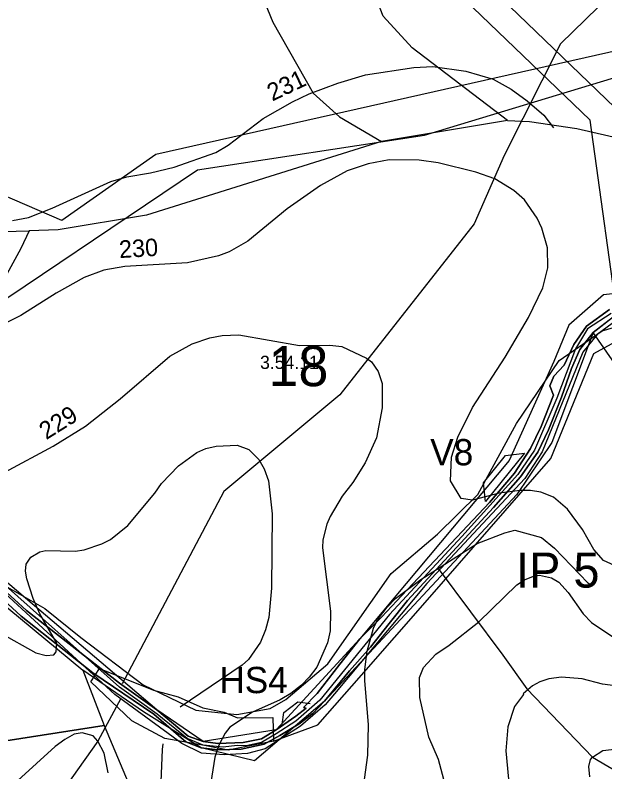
# Model space of a CAD drawing. Extents: x -662500 to -655523, y -1056000 to -1049993.
# Drawn here: x -661062 to -660725.5, y -1053298.7 to -1052866.9 of the extents above; entities that cross this region are included whole.
import ezdxf

# ---------------------------------------------------------------- set-up
doc = ezdxf.new("R2010")
doc.units = 0
for name, color, linetype in [('Vrstva 12', 7, 'Continuous'), ('Vrstva 17', 7, 'Continuous'), ('Vrstva 24', 7, 'Continuous'), ('Vrstva 37', 7, 'Continuous'), ('Vrstva 5', 7, 'Continuous'), ('Vrstva 51', 7, 'Continuous'), ('Vrstva 52', 7, 'Continuous'), ('Vrstva 57', 7, 'Continuous'), ('Vrstva 61', 7, 'Continuous'), ('Vrstva 7', 7, 'Continuous')]:
    doc.layers.add(name, color=color, linetype=linetype)

# ---------------------------------------------------------------- blocks, each defined once
blk = doc.blocks.new('PSZ019')
at = {"layer": 'Vrstva 17'}
blk.add_lwpolyline([(-10, -5), (-5, 0), (5, 0), (10, -5)], dxfattribs=at)

msp = doc.modelspace()

# ---------------------------------------------------------------- linework, layer by layer
at = {"layer": 'Vrstva 12'}
msp.add_lwpolyline([(-660721.83, -1053037.12), (-660735.32, -1053045.86), (-660742.25, -1053057.37), (-660752.91, -1053085.48), (-660765.65, -1053115.09), (-660775.15, -1053129.03), (-660807.08, -1053164.33), (-660848.44, -1053208.87), (-660888.22, -1053257.8), (-660901.81, -1053269.79), (-660913.13, -1053277.07), (-660921.52, -1053281.95), (-660930.22, -1053283.86), (-660935.33, -1053283.77), (-660943.41, -1053284.62), (-660954.65, -1053283.42), (-660963.95, -1053279.66), (-660981, -1053265.88), (-661002.51, -1053250.47), (-661074.82, -1053186.07), (-661095.06, -1053170.24), (-661358.37, -1053118.85)], dxfattribs=at)
at = {"layer": 'Vrstva 24'}
for points in [[(-660781, -1052927), (-660835.5, -1052885.5), (-660852, -1052867.5), (-660862.5, -1052840.5), (-660865.5, -1052804.5), (-660857.5, -1052768.5), (-660841.5, -1052741.5), (-660820.5, -1052719), (-660772, -1052687), (-660756.5, -1052680), (-660742.5, -1052678), (-660707.5, -1052679.5), (-660683, -1052682)], [(-660937.5, -1052816), (-660915, -1052871), (-660892, -1052911.5), (-660877, -1052925), (-660853, -1052939)], [(-660781, -1052927), (-660853, -1052939)], [(-660781, -1052927), (-660768.5, -1052927.5), (-660741.5, -1052931.5), (-660705, -1052940), (-660651.5, -1052959), (-660597, -1052987.5), (-660574.5, -1052991.5), (-660541.5, -1052988.5), (-660487, -1052969), (-660438.5, -1052947.5), (-660420, -1052937)], [(-660853, -1052939), (-660987, -1052981), (-661037.5, -1052989.5), (-661054, -1052990)], [(-661283, -1052945), (-661192.5, -1052974.5), (-661142.5, -1052986), (-661091, -1052991), (-661054, -1052990)], [(-661054, -1052990), (-661058.86, -1053000), (-661076, -1053031), (-661094, -1053081.5), (-661099.5, -1053135.5), (-661091.5, -1053170.5), (-661086.5, -1053182), (-661045, -1053205.5), (-661024.5, -1053222), (-660989, -1053249), (-660959, -1053263.5), (-660935.5, -1053266), (-660916.5, -1053262.5), (-660907.5, -1053257.5), (-660883.5, -1053237), (-660847.5, -1053185.5), (-660821, -1053163), (-660798, -1053140.5), (-660776, -1053100), (-660751.5, -1053064), (-660727, -1053047), (-660682.5, -1053034), (-660647, -1053031.5)]]:
    msp.add_lwpolyline(points, dxfattribs=at)
at = {"layer": 'Vrstva 37'}
msp.add_lwpolyline([(-661300.67, -1052546.9), (-661245.57, -1052460.16), (-661215.38, -1052383.27), (-661093.2, -1052036.62), (-661059.91, -1052039.12), (-661052.32, -1052039.28), (-660977.8, -1052048.89), (-660913.91, -1052057.78), (-660920.61, -1052206.16), (-660810.17, -1052287.05), (-660506.62, -1052383.42), (-660536.22, -1052464.9), (-660540.27, -1052493.39), (-660540.27, -1052503.48), (-660534.66, -1052516.97), (-660434.32, -1052493.61), (-660230.57, -1052568.54), (-660284.32, -1052681.97), (-660363.46, -1052667.73), (-660573.1, -1052736.64), (-660686.93, -1052879.97), (-660981.83, -1052946.49), (-661035.35, -1052984.09), (-661278.3, -1052879.13)], dxfattribs=at)
for points in [[(-661234.06, -1053140.82), (-660958.01, -1052955.16), (-660828.41, -1052935.32), (-660688.36, -1052892.92), (-660553.31, -1052789.11), (-660369.71, -1052706.96), (-660290.66, -1052724.21), (-660337.18, -1052820.64), (-660356.48, -1052923.15), (-660446.27, -1052991.51), (-660506.13, -1053013.32), (-660608.87, -1053013.32), (-660726.31, -1053026.56), (-660746.15, -1053043.81), (-660754.61, -1053064.64), (-660780.18, -1053120.96), (-660865.36, -1053222.79), (-660913.12, -1053274.78), (-660954.8, -1053281.43), (-660981.14, -1053263.41), (-661072.84, -1053185.46), (-661116.02, -1053160.8)], [(-661023.41, -1053240.67), (-661011.27, -1053272.33), (-660950.35, -1053416.85), (-660839.76, -1053380.96), (-660793.93, -1053380.96), (-660681.35, -1053517.53), (-660634.53, -1053539.46), (-660568.77, -1053550.42), (-660547.85, -1053511.55), (-660560.8, -1053426.81), (-660514.36, -1053361.25), (-660732.12, -1053048.02), (-660755.79, -1053110.82), (-660775.71, -1053140.44), (-660885.47, -1053258.33), (-660925.44, -1053292.53), (-660955.96, -1053285.06), (-660988.72, -1053264.41)], [(-661148.54, -1053166.72), (-661115.03, -1053173.55), (-661080.22, -1053193.73), (-661023.41, -1053240.67), (-661011.27, -1053272.33), (-661177.27, -1053298.13), (-661177.27, -1053193.32)], [(-661177.27, -1053298.13), (-661011.27, -1053272.33), (-660950.35, -1053416.85), (-660917.78, -1053483.08), (-660790.25, -1053532.64), (-660747.55, -1053569.67), (-660738.48, -1053593.77), (-660814.61, -1053668.4), (-661026.54, -1053571.34), (-661076.33, -1053536.24), (-661164.49, -1053527.45), (-661164.49, -1053425.3)]]:
    msp.add_lwpolyline(points, close=True, dxfattribs=at)
at = {"layer": 'Vrstva 5'}
for points in [[(-660722.76, -1053034.93), (-660735.98, -1053044.48), (-660743.18, -1053054.83), (-660748.68, -1053066.7), (-660754.58, -1053072.87), (-660756.89, -1053078.44), (-660754.9, -1053083.79), (-660761.93, -1053101.63), (-660767.89, -1053114.23), (-660777.07, -1053128.26), (-660791.34, -1053144.98), (-660841.41, -1053198.13), (-660852.69, -1053210.31), (-660865.36, -1053222.79), (-660876.66, -1053237.26), (-660889.7, -1053254.02), (-660897.41, -1053262.02), (-660895.91, -1053262.43), (-660901.79, -1053267.02), (-660913.12, -1053274.78), (-660921.53, -1053279.8), (-660931.83, -1053281.97), (-660946.36, -1053282.49), (-660954.8, -1053281.43), (-660963.29, -1053278.32), (-660981.14, -1053263.41), (-661002.45, -1053248.05), (-661055.62, -1053206.74), (-661080.49, -1053183.96)], [(-661080.49, -1053183.96), (-661055.62, -1053206.74), (-661002.45, -1053248.05), (-660981.14, -1053263.41), (-660963.29, -1053278.32), (-660954.8, -1053281.43), (-660946.36, -1053282.49), (-660931.83, -1053281.97), (-660921.53, -1053279.8), (-660913.12, -1053274.78), (-660901.79, -1053267.02), (-660895.91, -1053262.43), (-660897.41, -1053262.02), (-660889.7, -1053254.02), (-660876.66, -1053237.26), (-660865.36, -1053222.79), (-660852.69, -1053210.31), (-660841.41, -1053198.13), (-660791.34, -1053144.98), (-660777.07, -1053128.26), (-660767.89, -1053114.23), (-660761.93, -1053101.63), (-660754.9, -1053083.79), (-660756.89, -1053078.44), (-660754.58, -1053072.87), (-660748.68, -1053066.7), (-660743.18, -1053054.83), (-660735.98, -1053044.48), (-660722.76, -1053034.93)], [(-660720.59, -1053039.07), (-660732.12, -1053048.02), (-660739.81, -1053057.74), (-660744.56, -1053068.49), (-660750.25, -1053084.96), (-660757.59, -1053103.56), (-660763.8, -1053116.25), (-660773.68, -1053130.3), (-660789.03, -1053147.8), (-660838.07, -1053200.94), (-660848.58, -1053214.08), (-660859.32, -1053227.61), (-660871.21, -1053241.16), (-660885.47, -1053258.33), (-660892.03, -1053265.26), (-660899.88, -1053271.38), (-660910.94, -1053278.04), (-660919.86, -1053282.88), (-660933.05, -1053285.84), (-660946.32, -1053286.21), (-660955.96, -1053285.06), (-660964.6, -1053281.56), (-660982.89, -1053265.85), (-661017.69, -1053242.2), (-661058.53, -1053209.95), (-661076.54, -1053193.52)], [(-661076.54, -1053193.52), (-661058.53, -1053209.95), (-661017.69, -1053242.2), (-660982.89, -1053265.85), (-660964.6, -1053281.56), (-660955.96, -1053285.06), (-660946.32, -1053286.21), (-660933.05, -1053285.84), (-660919.86, -1053282.88), (-660910.94, -1053278.04), (-660899.88, -1053271.38), (-660892.03, -1053265.26), (-660885.47, -1053258.33), (-660871.21, -1053241.16), (-660859.32, -1053227.61), (-660848.58, -1053214.08), (-660838.07, -1053200.94), (-660789.03, -1053147.8), (-660773.68, -1053130.3), (-660763.8, -1053116.25), (-660757.59, -1053103.56), (-660750.25, -1053084.96), (-660744.56, -1053068.49), (-660739.81, -1053057.74), (-660732.12, -1053048.02), (-660721.62, -1053039.87)]]:
    msp.add_lwpolyline(points, dxfattribs=at)
at = {"layer": 'Vrstva 51'}
for points in [[(-661333.87, -1052639.96), (-661030.97, -1052722.69), (-660970.26, -1052748.97), (-660859.83, -1052784.77), (-660719.81, -1052919.67), (-660703.56, -1053036.33), (-660627.44, -1053034.97), (-660487.78, -1053023.58), (-660465.78, -1053017.23), (-660435.07, -1052998.4)], [(-660435.71, -1053016.39), (-660459.67, -1053031.08), (-660485.06, -1053038.41), (-660626.7, -1053049.96), (-660716.58, -1053051.57), (-660733.95, -1052926.87), (-660867.75, -1052797.97), (-660975.56, -1052763.02), (-661035.95, -1052736.88), (-661337.82, -1052654.43)]]:
    msp.add_lwpolyline(points, dxfattribs=at)
at = {"layer": 'Vrstva 52'}
msp.add_lwpolyline([(-660914.58, -1053281.25), (-660889.24, -1053271.93), (-660864.44, -1053243.57), (-660826.77, -1053200.49), (-660756.29, -1053119.89), (-660731.82, -1053060.03), (-660717.44, -1053052.21)], dxfattribs=at)
msp.add_lwpolyline([(-661018.88, -1053247.39), (-661013.86, -1053239.75), (-660983.14, -1053252.18), (-660969.07, -1053255.98), (-660954.84, -1053262.25), (-660942.72, -1053264.73), (-660935.12, -1053267.87), (-660915.07, -1053267.7), (-660914.58, -1053281.25), (-660940.45, -1053286.36), (-660954.04, -1053283.72), (-660976.67, -1053279.76), (-660995.43, -1053269.69)], close=True, dxfattribs=at)
at = {"layer": 'Vrstva 57'}
for points in [[(-660686.61, -1052820.49), (-660750.76, -1052883.23), (-660782.95, -1052946.91), (-660800.11, -1052985.92), (-660876.71, -1053083.67), (-660942.98, -1053138.66), (-661001.03, -1053248.46)], [(-660820.67, -1053182.66), (-660783.66, -1053232.18), (-660770.03, -1053251.45), (-660732.62, -1053290.28), (-660657.94, -1053334.16), (-660629.74, -1053356.96), (-660614.23, -1053378.11), (-660607.65, -1053423.22), (-660606.24, -1053447.66)], [(-661001.72, -1053256.85), (-661014.78, -1053281.21), (-661058.43, -1053342.72), (-661096.89, -1053410.3), (-661108.64, -1053470.92)]]:
    msp.add_lwpolyline(points, dxfattribs=at)
at = {"layer": 'Vrstva 61'}
msp.add_lwpolyline([(-660718.55, -1053040.85), (-660729.86, -1053049.1), (-660738.1, -1053059.21), (-660761.33, -1053116.11), (-660771.24, -1053131.38), (-660827.02, -1053191.27), (-660879.82, -1053254.25), (-660885.04, -1053260.47), (-660899.16, -1053272.63), (-660919.42, -1053285.57), (-660929.53, -1053288.23), (-660942.75, -1053288.99), (-660955.65, -1053288.03), (-660966.97, -1053282.64), (-661005.21, -1053254.62), (-661075.25, -1053190.17), (-661096.03, -1053172.53), (-661234.7, -1053147.1), (-661269.14, -1053141.65)], dxfattribs=at)
msp.add_lwpolyline([(-660793.53, -1053144.41), (-660794.68, -1053133.86), (-660782.14, -1053118.28), (-660771.43, -1053116.93)], close=True, dxfattribs=at)
at = {"layer": 'Vrstva 7'}
for p, q in [((-660862.01, -1052900.99), (-660834.51, -1052896.74)), ((-660834.51, -1052896.74), (-660823.74, -1052896.17)), ((-660823.74, -1052896.17), (-660804.89, -1052898.86)), ((-660804.89, -1052898.86), (-660789.16, -1052903.4)), ((-660877.88, -1052905.8), (-660862.01, -1052900.99)), ((-660789.16, -1052903.4), (-660778.96, -1052909.21)), ((-660894.18, -1052911.76), (-660877.88, -1052905.8)), ((-660903.75, -1052916.29), (-660894.18, -1052911.76)), ((-660778.96, -1052909.21), (-660769.89, -1052915.73)), ((-660920.53, -1052925.93), (-660903.75, -1052916.29)), ((-660769.89, -1052915.73), (-660760.4, -1052923.94)), ((-660940.52, -1052941.09), (-660920.53, -1052925.93)), ((-660760.4, -1052923.94), (-660754.73, -1052931.17)), ((-660947.6, -1052945.34), (-660940.52, -1052941.09)), ((-660971.27, -1052953.56), (-660947.6, -1052945.34)), ((-660860.59, -1052951.72), (-660872.49, -1052955.69)), ((-660848.68, -1052949.45), (-660860.59, -1052951.72)), ((-660831.4, -1052949.59), (-660848.68, -1052949.45)), ((-660820.62, -1052951.15), (-660831.4, -1052949.59)), ((-660799.08, -1052956.54), (-660820.62, -1052951.15)), ((-660984.73, -1052956.96), (-660971.27, -1052953.56)), ((-660872.49, -1052955.69), (-660887.8, -1052964.05)), ((-661007.41, -1052961.92), (-660998.34, -1052959.23)), ((-660998.34, -1052959.23), (-660984.73, -1052956.96)), ((-660788.31, -1052960.37), (-660799.08, -1052956.54)), ((-660777.54, -1052967.03), (-660788.31, -1052960.37)), ((-661040.85, -1052977.09), (-661007.41, -1052961.92)), ((-660887.8, -1052964.05), (-660906.79, -1052977.37)), ((-660771.31, -1052972.27), (-660777.54, -1052967.03)), ((-660764.22, -1052982.76), (-660771.31, -1052972.27)), ((-661054.46, -1052982.47), (-661040.85, -1052977.09)), ((-660906.79, -1052977.37), (-660929.18, -1052995.79)), ((-661063.53, -1052984.17), (-661054.46, -1052982.47)), ((-660761.53, -1052988.43), (-660764.22, -1052982.76)), ((-660758.27, -1052999.76), (-660761.53, -1052988.43)), ((-660929.18, -1052995.79), (-660939.95, -1053001.89)), ((-660939.95, -1053001.89), (-660945.9, -1053004.3)), ((-660758.13, -1053011.1), (-660758.27, -1052999.76)), ((-660963.76, -1053008.27), (-660999.47, -1053010.39)), ((-660945.9, -1053004.3), (-660963.76, -1053008.27)), ((-661011.38, -1053012.38), (-661022.71, -1053016.63)), ((-660999.47, -1053010.39), (-661011.38, -1053012.38)), ((-660760.82, -1053022.44), (-660758.13, -1053011.1)), ((-661022.71, -1053016.63), (-661038.58, -1053025.55)), ((-661038.58, -1053025.55), (-661058.71, -1053038.31)), ((-660769.04, -1053039.44), (-660760.82, -1053022.44)), ((-661058.71, -1053038.31), (-661069.48, -1053043.7)), ((-660782.36, -1053062.12), (-660769.04, -1053039.44)), ((-660960.92, -1053054.47), (-660951, -1053051.06)), ((-660951, -1053051.06), (-660943.92, -1053049.65)), ((-660943.92, -1053049.65), (-660934.42, -1053049.36)), ((-660934.42, -1053049.36), (-660899.7, -1053055.46)), ((-660973.68, -1053061.55), (-660960.92, -1053054.47)), ((-660899.7, -1053055.46), (-660882.41, -1053055.31)), ((-660882.41, -1053055.31), (-660875.61, -1053056.02)), ((-660875.61, -1053056.02), (-660861.44, -1053062.68)), ((-661002.16, -1053085.78), (-660973.68, -1053061.55)), ((-660861.44, -1053062.68), (-660858.75, -1053064.81)), ((-660801.07, -1053090.75), (-660782.36, -1053062.12)), ((-660858.75, -1053064.81), (-660854.92, -1053070.34)), ((-660854.92, -1053070.34), (-660852.65, -1053077.14)), ((-660852.65, -1053077.14), (-660852.51, -1053091.03)), ((-661021.86, -1053101.37), (-661002.16, -1053085.78)), ((-660852.51, -1053091.03), (-660855.77, -1053108.18)), ((-660809.43, -1053107.75), (-660801.07, -1053090.75)), ((-661040.29, -1053112.85), (-661021.86, -1053101.37)), ((-660855.77, -1053108.18), (-660862.2, -1053122.38)), ((-660813.11, -1053119.09), (-660809.43, -1053107.75)), ((-661067.92, -1053127.73), (-661040.29, -1053112.85)), ((-660958.37, -1053116.54), (-660953.27, -1053114.27)), ((-660953.27, -1053114.27), (-660947.32, -1053112.85)), ((-660947.32, -1053112.85), (-660935.42, -1053112.28)), ((-660935.42, -1053112.28), (-660928.61, -1053114.7)), ((-660928.61, -1053114.7), (-660922.94, -1053120.51)), ((-660968.86, -1053124.19), (-660958.37, -1053116.54)), ((-660922.94, -1053120.51), (-660919.83, -1053125.89)), ((-660813.54, -1053132.69), (-660813.11, -1053119.09)), ((-660978.5, -1053134.11), (-660968.86, -1053124.19)), ((-660862.2, -1053122.38), (-660869.38, -1053133.69)), ((-660919.83, -1053125.89), (-660917.42, -1053132.69)), ((-660917.42, -1053132.69), (-660915.43, -1053151.4)), ((-660807.45, -1053142.76), (-660813.54, -1053132.69)), ((-660982.32, -1053139.78), (-660978.5, -1053134.11)), ((-660869.38, -1053133.69), (-660875.47, -1053141.48)), ((-660997.77, -1053158.2), (-660982.32, -1053139.78)), ((-660875.47, -1053141.48), (-660882.27, -1053153.1)), ((-660785.76, -1053139.78), (-660801.07, -1053143.75)), ((-660773.86, -1053138.08), (-660785.76, -1053139.78)), ((-660767.91, -1053138.08), (-660773.86, -1053138.08)), ((-660761.95, -1053139.07), (-660767.91, -1053138.08)), ((-660754.73, -1053141.9), (-660761.95, -1053139.07)), ((-660746.79, -1053148.85), (-660754.73, -1053141.9)), ((-660801.07, -1053143.75), (-660807.45, -1053142.76)), ((-660738.29, -1053160.47), (-660746.79, -1053148.85)), ((-660915.43, -1053151.4), (-660915.72, -1053193.91)), ((-660882.27, -1053153.1), (-660884.11, -1053157.35)), ((-661007.69, -1053166.14), (-660997.77, -1053158.2)), ((-660884.11, -1053157.35), (-660886.38, -1053166.28)), ((-660798.38, -1053168.41), (-660782.64, -1053162.31)), ((-660782.64, -1053162.31), (-660776.83, -1053160.75)), ((-660776.83, -1053160.75), (-660761.64, -1053165.03)), ((-660731.77, -1053171.81), (-660738.29, -1053160.47)), ((-661012.51, -1053168.69), (-661007.69, -1053166.14)), ((-660886.38, -1053166.28), (-660886.66, -1053170.81)), ((-660761.64, -1053165.03), (-660754.16, -1053171.1)), ((-661047.94, -1053173.22), (-661044.54, -1053172.37)), ((-661044.54, -1053172.37), (-661027.81, -1053172.8)), ((-661027.81, -1053172.8), (-661022.71, -1053171.95)), ((-661022.71, -1053171.95), (-661012.51, -1053168.69)), ((-660886.66, -1053170.81), (-660882.13, -1053206.95)), ((-660830.55, -1053188.95), (-660798.38, -1053168.41)), ((-660754.16, -1053171.1), (-660735.17, -1053190.8)), ((-660726.24, -1053178.18), (-660731.77, -1053171.81)), ((-661055.73, -1053180.17), (-661053.04, -1053176.2)), ((-661053.04, -1053176.2), (-661047.94, -1053173.22)), ((-661056.16, -1053184.14), (-661055.73, -1053180.17)), ((-660715.75, -1053182.86), (-660726.24, -1053178.18)), ((-661055.45, -1053188.53), (-661056.16, -1053184.14)), ((-661051.76, -1053199.87), (-661055.45, -1053188.53)), ((-660845, -1053199.73), (-660830.55, -1053188.95)), ((-660775.7, -1053191.93), (-660771.31, -1053189.1)), ((-660771.31, -1053189.1), (-660766.2, -1053187.11)), ((-660766.2, -1053187.11), (-660762.8, -1053186.54)), ((-660762.8, -1053186.54), (-660756, -1053188.1)), ((-660756, -1053188.1), (-660751.75, -1053190.51)), ((-660915.72, -1053193.91), (-660917.28, -1053210.64)), ((-660797.38, -1053213.05), (-660775.7, -1053191.93)), ((-660751.75, -1053190.51), (-660746.51, -1053196.47)), ((-660735.17, -1053190.8), (-660732.9, -1053192.21)), ((-660746.51, -1053196.47), (-660737.86, -1053208.65)), ((-661047.94, -1053208.65), (-661051.76, -1053199.87)), ((-660849.68, -1053204.69), (-660845, -1053199.73)), ((-660882.13, -1053206.95), (-660882.27, -1053218.29)), ((-660855.25, -1053212.04), (-660849.68, -1053204.69)), ((-661038.16, -1053225.23), (-661047.94, -1053208.65)), ((-660917.28, -1053210.64), (-660919.12, -1053217.72)), ((-660737.86, -1053208.65), (-660733.04, -1053213.47)), ((-660857.52, -1053216.65), (-660855.25, -1053212.04)), ((-660814.39, -1053226.37), (-660797.38, -1053213.05)), ((-660733.04, -1053213.47), (-660719.72, -1053222.4)), ((-661070.75, -1053219.42), (-661050.2, -1053230.76)), ((-660919.12, -1053217.72), (-660922.09, -1053224.81)), ((-660882.27, -1053218.29), (-660883.83, -1053225.09)), ((-660861.21, -1053229.89), (-660857.52, -1053216.65)), ((-661038.58, -1053230.19), (-661038.16, -1053225.23)), ((-660922.09, -1053224.81), (-660928.9, -1053234.59)), ((-660883.83, -1053225.09), (-660889.92, -1053238.98)), ((-660822.04, -1053231.61), (-660814.39, -1053226.37)), ((-661050.2, -1053230.76), (-661044.25, -1053232.32)), ((-661044.25, -1053232.32), (-661040, -1053231.89)), ((-661040, -1053231.89), (-661038.58, -1053230.19)), ((-660862.43, -1053240.26), (-660861.21, -1053229.89)), ((-660828.98, -1053239.12), (-660822.04, -1053231.61)), ((-660928.9, -1053234.59), (-660932.44, -1053237.85)), ((-660932.44, -1053237.85), (-660967.79, -1053261.85)), ((-660889.92, -1053238.98), (-660894.18, -1053244.65)), ((-660862.43, -1053246.63), (-660862.43, -1053240.26)), ((-660831.27, -1053244.94), (-660828.98, -1053239.12)), ((-660894.18, -1053244.65), (-660898.57, -1053249.18)), ((-660831.11, -1053256.27), (-660831.27, -1053244.94)), ((-660757.42, -1053245.73), (-660762.65, -1053247.33)), ((-660750.19, -1053244.65), (-660757.42, -1053245.73)), ((-660738.43, -1053245.64), (-660750.19, -1053244.65)), ((-660726.81, -1053248.76), (-660738.43, -1053245.64)), ((-660898.57, -1053249.18), (-660904.8, -1053254)), ((-660860.31, -1053271.86), (-660862.43, -1053246.63)), ((-660766.75, -1053249.73), (-660772.16, -1053254.14)), ((-660762.65, -1053247.33), (-660766.75, -1053249.73)), ((-660712.92, -1053250.6), (-660726.81, -1053248.76)), ((-660904.8, -1053254), (-660910.76, -1053257.54)), ((-660772.16, -1053254.14), (-660771.87, -1053254.57)), ((-660910.76, -1053257.54), (-660926.63, -1053264.63)), ((-660826.01, -1053278.94), (-660831.11, -1053256.27)), ((-660771.87, -1053254.57), (-660777.12, -1053261.51)), ((-660777.12, -1053261.51), (-660780.8, -1053272.99)), ((-660926.63, -1053264.63), (-660939.52, -1053273.28)), ((-660939.52, -1053273.28), (-660942.22, -1053276.68)), ((-660860.73, -1053289.29), (-660860.31, -1053271.86)), ((-660780.8, -1053272.99), (-660781.94, -1053286.74)), ((-661033.77, -1053280.22), (-661039.15, -1053284.33)), ((-661028.38, -1053277.24), (-661033.77, -1053280.22)), ((-661023.85, -1053276.53), (-661028.38, -1053277.24)), ((-661017.47, -1053278.09), (-661023.85, -1053276.53)), ((-661014.78, -1053281.21), (-661017.47, -1053278.09)), ((-660942.22, -1053276.68), (-660945.76, -1053283.48)), ((-660820.48, -1053291.7), (-660826.01, -1053278.94)), ((-661039.15, -1053284.33), (-661060.55, -1053303.6)), ((-661011.23, -1053288.01), (-661014.78, -1053281.21)), ((-660977.83, -1053282.67), (-660978.07, -1053286.03)), ((-660945.76, -1053283.48), (-660948.17, -1053290.28)), ((-661008.97, -1053299.35), (-661011.23, -1053288.01)), ((-660978.07, -1053286.03), (-660979.63, -1053321.74)), ((-660781.94, -1053286.74), (-660779.24, -1053315.79)), ((-660732.62, -1053290.28), (-660726.67, -1053286.6)), ((-660726.67, -1053286.6), (-660713.49, -1053285.04)), ((-660948.17, -1053290.28), (-660951, -1053308.42)), ((-660862.71, -1053303.04), (-660860.73, -1053289.29)), ((-660816.66, -1053305.87), (-660820.48, -1053291.7)), ((-660734.74, -1053295.67), (-660733.75, -1053291.7)), ((-660733.75, -1053291.7), (-660732.62, -1053290.28)), ((-660734.04, -1053301.62), (-660734.74, -1053295.67))]:
    msp.add_line(p, q, dxfattribs=at)

# ---------------------------------------------------------------- block references
at = {"layer": 'Vrstva 17', "rotation": 36.78707845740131}
msp.add_blockref('PSZ019', (-660904.65, -1053261.79), dxfattribs=at)

# ---------------------------------------------------------------- texts
at = {"layer": 'Vrstva 17'}
msp.add_text('HS4', height=15, rotation=360, dxfattribs=at).set_placement((-660945.5, -1053253.82))
at = {"layer": 'Vrstva 24'}
msp.add_text('3.54.11', height=7.5, dxfattribs=at).set_placement((-660922.25, -1053068.8))
at = {"layer": 'Vrstva 52'}
msp.add_text('IP 5', height=20, dxfattribs=at).set_placement((-660776.14, -1053193.59))
at = {"layer": 'Vrstva 57'}
msp.add_text('18', height=23, dxfattribs=at).set_placement((-660917.48, -1053078.62))
at = {"layer": 'Vrstva 61'}
msp.add_text('V8', height=15, dxfattribs=at).set_placement((-660825.15, -1053123.81))
at = {"layer": 'Vrstva 7'}
for s, rotation, p in [('231', 25.341, (-660915.28, -1052916.22)), ('230', 3.4068, (-661002.46, -1053005.56)), ('229', 31.9262, (-661044.31, -1053109.46))]:
    msp.add_text(s, height=10, rotation=rotation, dxfattribs=at).set_placement(p)

doc.saveas('drawing.dxf')
